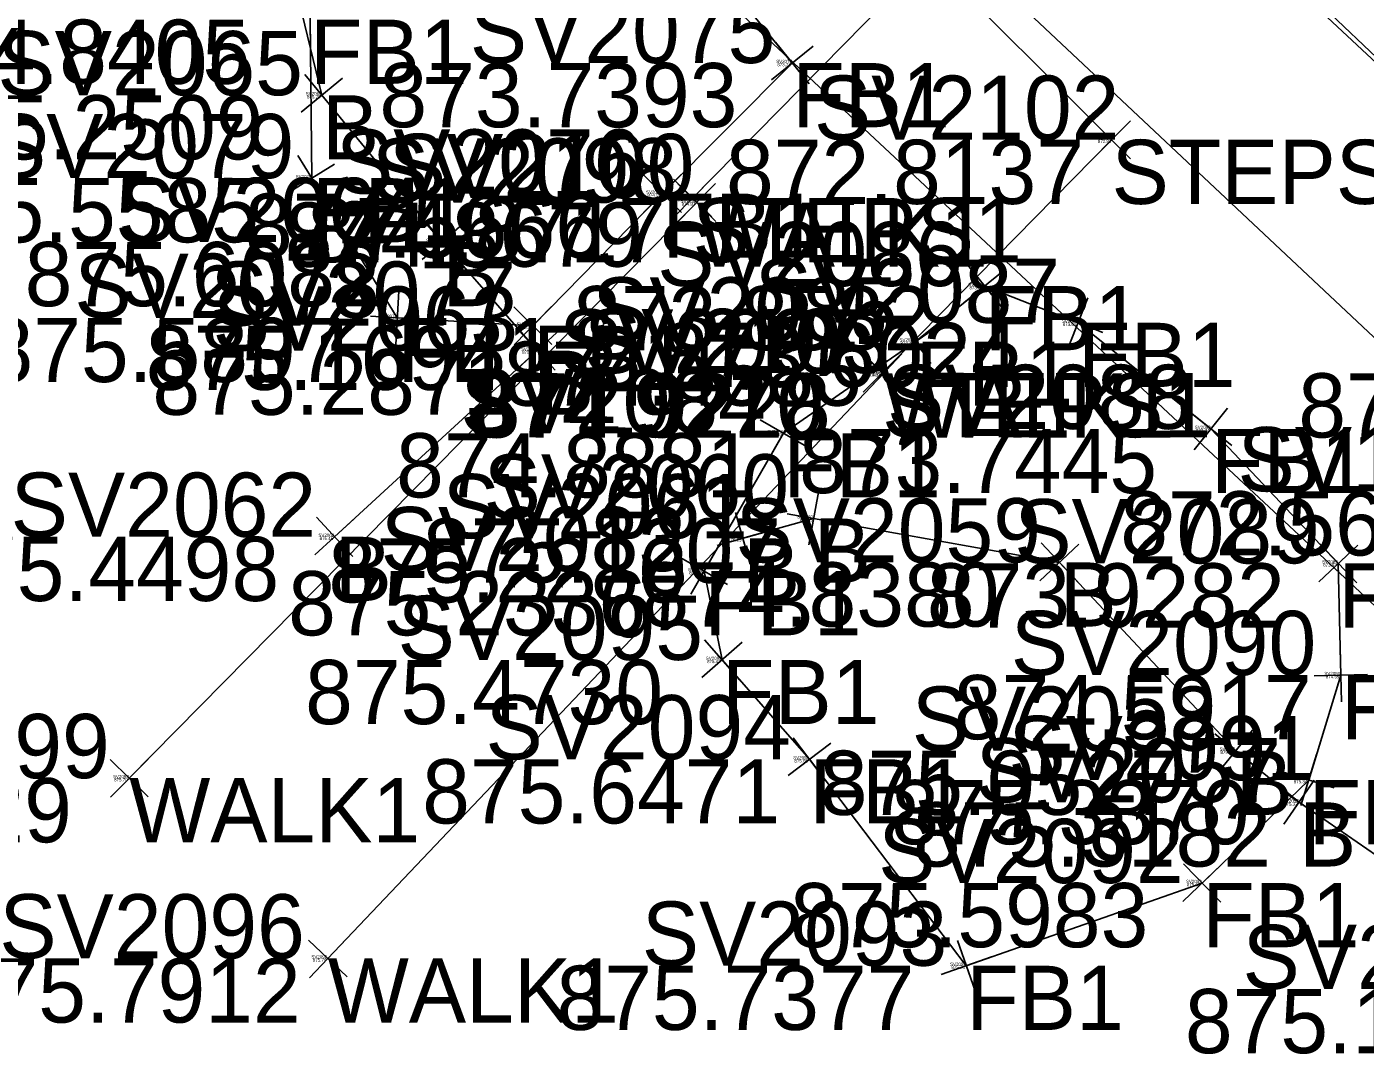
# Model space of a CAD drawing. Extents: x 1469677 to 1493262, y 375219 to 389293.
# Drawn here: x 1480055.3 to 1480080.32, y 379461.81 to 379481.19 of the extents above; entities that cross this region are included whole.
import ezdxf

# ---------------------------------------------------------------- set-up
doc = ezdxf.new("R2010")
doc.units = 0
for name, color, linetype in [('DR_X_Drive_Pipe', 7, 'Continuous'), ('DV_X_Lot_Line', 7, 'Continuous'), ('DV_X_Text', 7, 'Continuous'), ('GK_Visualization', 7, 'Continuous'), ('PNTELEV', 7, 'Continuous'), ('Property', 7, 'Continuous'), ('RW_P_Esmt_SW', 7, 'Continuous'), ('SV_X_Mon_Cells_Found', 7, 'Continuous'), ('text', 7, 'Continuous'), ('Text Property', 7, 'Continuous')]:
    doc.layers.add(name, color=color, linetype=linetype)

msp = doc.modelspace()

# ---------------------------------------------------------------- linework, layer by layer
at = {"layer": 'DR_X_Drive_Pipe'}
msp.add_lwpolyline([(1480134.739, 379430.559), (1480121.485, 379441.998), (1480113.085, 379450.369), (1480106.418, 379456.915), (1480094.539, 379467.985), (1480089.15, 379472.551), (1480086.751, 379474.713), (1480073.459, 379487.337), (1480068.123, 379493.187), (1480050.678, 379510.207), (1480044.404, 379515.873)], dxfattribs=at)
at = {"layer": 'DV_X_Lot_Line'}
for points in [[(1480132.903, 379425.968), (1480114.834, 379442.96), (1480103.251, 379453.811), (1480091.01, 379465.628), (1480083.545, 379472.507), (1480065.123, 379489.824), (1480051.079, 379503.111), (1480050.67, 379503.609), (1480040.657, 379513.03), (1480041.273, 379513.837), (1480027.417, 379527.179), (1480013.329, 379540.204)], [(1480053.564, 379505.61), (1480071.797, 379488.664), (1480089.369, 379472.273), (1480095.978, 379465.936)], [(1480067.823, 379477.906), (1480057.214, 379467.144)], [(1480060.926, 379463.774), (1480071.315, 379474.711)]]:
    msp.add_lwpolyline(points, dxfattribs=at)
at = {"layer": 'PNTELEV'}
for p, q in [((1480060.6, 379480.825), (1480060.588, 379481.825)), ((1480069.295, 379480.903), (1480069.923, 379480.125)), ((1480069.998, 379480.828), (1480069.22, 379480.2)), ((1480069.609, 379480.514), (1480069.609, 379480.514)), ((1480060.429, 379479.595), (1480061.203, 379480.229)), ((1480061.133, 379479.525), (1480060.499, 379480.299)), ((1480060.816, 379479.912), (1480060.816, 379479.912)), ((1480075.224, 379479.432), (1480075.932, 379478.725)), ((1480075.931, 379479.432), (1480075.225, 379478.725)), ((1480075.578, 379479.079), (1480075.578, 379479.079)), ((1480060.201, 379478.101), (1480061.053, 379478.623)), ((1480060.888, 379477.935), (1480060.366, 379478.788)), ((1480060.627, 379478.362), (1480060.627, 379478.362)), ((1480067.535, 379477.72), (1480066.827, 379478.426)), ((1480067.534, 379478.427), (1480066.828, 379477.719)), ((1480067.396, 379477.633), (1480068.096, 379478.347)), ((1480067.389, 379478.34), (1480068.103, 379477.64)), ((1480068.179, 379477.554), (1480067.467, 379478.257)), ((1480068.174, 379478.262), (1480067.472, 379477.549)), ((1480067.181, 379478.073), (1480067.181, 379478.073)), ((1480067.746, 379477.99), (1480067.746, 379477.99)), ((1480067.823, 379477.906), (1480067.823, 379477.906)), ((1480062.687, 379476.839), (1480063.439, 379477.497)), ((1480063.392, 379476.792), (1480062.734, 379477.544)), ((1480063.063, 379477.168), (1480063.063, 379477.168)), ((1480072.816, 379476.031), (1480073.596, 379476.658)), ((1480072.893, 379476.734), (1480073.519, 379475.955)), ((1480073.206, 379476.344), (1480073.206, 379476.344)), ((1480062.196, 379475.251), (1480062.254, 379476.249)), ((1480075.134, 379476.123), (1480074.768, 379475.192)), ((1480065.116, 379475.253), (1480064.402, 379475.953)), ((1480065.109, 379475.96), (1480064.409, 379475.246)), ((1480074.486, 379475.841), (1480075.416, 379475.475)), ((1480062.724, 379475.721), (1480061.726, 379475.779)), ((1480062.225, 379475.75), (1480062.225, 379475.75)), ((1480064.759, 379475.603), (1480064.759, 379475.603)), ((1480071.504, 379475.022), (1480072.326, 379475.591)), ((1480071.63, 379475.718), (1480072.2, 379474.896)), ((1480074.951, 379475.658), (1480074.951, 379475.658)), ((1480064.47, 379474.799), (1480065.206, 379475.476)), ((1480064.5, 379475.505), (1480065.176, 379474.769)), ((1480064.838, 379475.137), (1480064.838, 379475.137)), ((1480071.915, 379475.307), (1480071.915, 379475.307)), ((1480071.644, 379474.366), (1480070.932, 379475.067)), ((1480071.639, 379475.073), (1480070.937, 379474.36)), ((1480070.952, 379475.056), (1480071.678, 379474.367)), ((1480070.971, 379474.349), (1480071.659, 379475.074)), ((1480071.288, 379474.717), (1480071.288, 379474.717)), ((1480071.315, 379474.711), (1480071.315, 379474.711)), ((1480069.008, 379473.842), (1480069.876, 379473.344)), ((1480069.193, 379473.16), (1480069.691, 379474.027)), ((1480077.045, 379473.985), (1480077.827, 379473.361)), ((1480077.748, 379474.064), (1480077.124, 379473.283)), ((1480069.442, 379473.593), (1480069.442, 379473.593)), ((1480077.436, 379473.673), (1480077.436, 379473.673)), ((1480069.92, 379471.507), (1480070.096, 379472.491)), ((1480068.82, 379471.147), (1480068.55, 379472.11)), ((1480070.5, 379471.911), (1480069.516, 379472.087)), ((1480060.685, 379471.318), (1480061.421, 379471.994)), ((1480060.715, 379472.024), (1480061.391, 379471.288)), ((1480070.008, 379471.999), (1480070.008, 379471.999)), ((1480061.053, 379471.656), (1480061.053, 379471.656)), ((1480069.167, 379471.764), (1480068.203, 379471.494)), ((1480068.685, 379471.629), (1480068.685, 379471.629)), ((1480067.712, 379470.581), (1480068.21, 379471.448)), ((1480074.239, 379470.836), (1480074.969, 379471.519)), ((1480074.946, 379470.813), (1480074.262, 379471.543)), ((1480080.179, 379471.503), (1480079.453, 379470.816)), ((1480079.472, 379471.523), (1480080.16, 379470.797)), ((1480067.527, 379471.263), (1480068.395, 379470.765)), ((1480074.604, 379471.178), (1480074.604, 379471.178)), ((1480079.816, 379471.16), (1480079.816, 379471.16)), ((1480067.961, 379471.014), (1480067.961, 379471.014)), ((1480067.921, 379469.024), (1480068.671, 379469.685)), ((1480068.626, 379468.979), (1480067.966, 379469.73)), ((1480068.296, 379469.354), (1480068.296, 379469.354)), ((1480079.853, 379469.57), (1480079.875, 379468.571)), ((1480080.364, 379469.082), (1480079.364, 379469.059)), ((1480079.864, 379469.071), (1480079.864, 379469.071)), ((1480070.232, 379467.099), (1480069.628, 379467.895)), ((1480078.287, 379467.341), (1480077.511, 379467.973)), ((1480077.583, 379467.269), (1480078.215, 379468.044)), ((1480069.532, 379467.194), (1480070.328, 379467.799)), ((1480077.899, 379467.657), (1480077.899, 379467.657)), ((1480079.41, 379467.587), (1480079.118, 379466.63)), ((1480057.57, 379466.793), (1480056.858, 379467.495)), ((1480057.565, 379467.5), (1480056.863, 379466.788)), ((1480069.93, 379467.497), (1480069.93, 379467.497)), ((1480057.214, 379467.144), (1480057.214, 379467.144)), ((1480079.742, 379466.962), (1480078.786, 379467.255)), ((1480078.799, 379466.281), (1480079.367, 379467.104)), ((1480079.264, 379467.108), (1480079.264, 379467.108)), ((1480079.495, 379466.409), (1480078.671, 379466.976)), ((1480079.083, 379466.692), (1480079.083, 379466.692)), ((1480077.632, 379465.531), (1480076.912, 379464.836)), ((1480077.619, 379464.824), (1480076.925, 379465.543)), ((1480077.272, 379465.183), (1480077.272, 379465.183)), ((1480060.563, 379464.118), (1480061.289, 379463.429)), ((1480060.582, 379463.411), (1480061.27, 379464.136)), ((1480073.027, 379463.165), (1480072.697, 379464.109)), ((1480060.926, 379463.774), (1480060.926, 379463.774)), ((1480073.334, 379463.802), (1480072.39, 379463.471)), ((1480072.862, 379463.637), (1480072.862, 379463.637))]:
    msp.add_line(p, q, dxfattribs=at)
at = {"layer": 'Property'}
msp.add_lwpolyline([(1480067.746, 379477.99), (1480072.165, 379482.489), (1480075.578, 379479.079), (1480071.288, 379474.717)], dxfattribs=at)
at = {"layer": 'SV_X_Mon_Cells_Found'}
msp.add_lwpolyline([(1477164.629, 382297.849), (1479615.888, 379904.59), (1480413.414, 379159.216)], dxfattribs=at)
at = {"layer": 'text'}
for points in [[(1480061.053, 379471.656), (1480064.838, 379475.137), (1480063.063, 379477.168), (1480060.816, 379479.912), (1480059.959, 379483.437), (1480053.932, 379487.957), (1480050.898, 379492.776), (1480048.55, 379495.74), (1480045.746, 379494.465)], [(1480079.005, 379447.144), (1480081.842, 379450.534), (1480085.618, 379454.399), (1480087.323, 379457.733), (1480087.179, 379459.291), (1480084.148, 379463.202), (1480079.083, 379466.692), (1480077.899, 379467.657), (1480074.604, 379471.178), (1480070.008, 379471.999), (1480068.685, 379471.629)]]:
    msp.add_lwpolyline(points, dxfattribs=at)
at = {"layer": 'Text Property'}
for points in [[(1480060.934, 379485.44), (1480063.531, 379485.366), (1480068.028, 379482.471), (1480069.609, 379480.514), (1480067.181, 379478.073), (1480064.759, 379475.603), (1480062.225, 379475.75), (1480060.627, 379478.362), (1480060.594, 379481.325), (1480060.963, 379484.307), (1480062.027, 379485.899)], [(1480067.961, 379471.014), (1480069.442, 379473.593), (1480071.915, 379475.307), (1480073.206, 379476.344), (1480074.951, 379475.658), (1480077.436, 379473.673), (1480079.816, 379471.16), (1480079.864, 379469.071), (1480079.264, 379467.108), (1480077.272, 379465.183), (1480072.862, 379463.637), (1480069.93, 379467.497), (1480068.296, 379469.354)]]:
    msp.add_lwpolyline(points, close=True, dxfattribs=at)

# ---------------------------------------------------------------- texts
at = {"layer": 'DV_X_Text'}
for s, height, p in [('874.8405', 1.2, (1480052.781, 379480.125)), ('873.7393', 1.2, (1480061.89, 379479.314)), ('873.74', 0.06, (1480069.329, 379480.454)), ('875.2509', 1.2, (1480053.031, 379478.712)), ('875.25', 0.06, (1480060.537, 379479.852)), ('872.8137', 1.2, (1480068.37, 379477.879)), ('872.81', 0.06, (1480075.321, 379479.019)), ('875.5585', 1.2, (1480052.946, 379477.162)), ('875.56', 0.06, (1480060.343, 379478.302)), ('874.5666', 1.2, (1480059.377, 379476.873)), ('874.8679', 1.2, (1480060.123, 379476.706)), ('874.8717', 1.2, (1480060.547, 379476.79)), ('874.57', 0.06, (1480066.9, 379478.013)), ('874.87', 0.06, (1480067.465, 379477.93)), ('874.87', 0.06, (1480067.542, 379477.846)), ('875.6082', 1.2, (1480055.259, 379475.968)), ('875.61', 0.06, (1480062.804, 379477.108)), ('873.8582', 1.2, (1480065.515, 379475.144)), ('873.86', 0.06, (1480072.921, 379476.284)), ('875.5897', 1.2, (1480054.525, 379474.55)), ('875.1694', 1.2, (1480057.522, 379474.403)), ('875.59', 0.06, (1480061.944, 379475.69)), ('875.17', 0.06, (1480064.503, 379475.543)), ('873.6024', 1.2, (1480067.147, 379474.458)), ('873.60', 0.06, (1480074.664, 379475.598)), ('875.2871', 1.2, (1480057.646, 379473.937)), ('874.4585', 1.2, (1480064.215, 379474.107)), ('875.29', 0.06, (1480064.558, 379475.077)), ('874.46', 0.06, (1480071.63, 379475.247)), ('874.9270', 1.2, (1480063.512, 379473.517)), ('874.9228', 1.2, (1480063.634, 379473.511)), ('874.93', 0.06, (1480071.006, 379474.657)), ('874.92', 0.06, (1480071.034, 379474.651)), ('872.5987', 1.2, (1480079.069, 379473.513)), ('874.8881', 1.2, (1480062.202, 379472.393)), ('874.89', 0.06, (1480069.161, 379473.533)), ('873.7445', 1.2, (1480069.736, 379472.473)), ('873.74', 0.06, (1480077.156, 379473.613)), ('872.5608', 1.2, (1480075.741, 379471.307)), ('875.1207', 1.2, (1480062.705, 379470.799)), ('875.12', 0.06, (1480069.752, 379471.939)), ('875.4498', 1.2, (1480053.324, 379470.456)), ('875.45', 0.06, (1480060.772, 379471.596)), ('875.2280', 1.2, (1480060.937, 379470.429)), ('875.23', 0.06, (1480068.406, 379471.569)), ('874.8380', 1.2, (1480066.79, 379469.978)), ('873.9282', 1.2, (1480072.125, 379469.96)), ('874.84', 0.06, (1480074.324, 379471.118)), ('873.93', 0.06, (1480079.534, 379471.1)), ('875.2336', 1.2, (1480060.185, 379469.814)), ('875.23', 0.06, (1480067.682, 379470.954)), ('875.4730', 1.2, (1480060.501, 379468.154)), ('875.47', 0.06, (1480068.015, 379469.294)), ('874.5917', 1.2, (1480072.627, 379467.871)), ('874.59', 0.06, (1480079.583, 379469.011)), ('875.0527', 1.2, (1480070.123, 379466.457)), ('875.05', 0.06, (1480077.613, 379467.597)), ('875.6471', 1.2, (1480062.69, 379466.297)), ('875.65', 0.06, (1480069.649, 379467.437)), ('875.7029', 1.2, (1480049.448, 379465.944)), ('875.70', 0.06, (1480056.93, 379467.084)), ('875.3370', 1.2, (1480071.46, 379465.908)), ('875.34', 0.06, (1480078.983, 379467.048)), ('875.3182', 1.2, (1480071.865, 379465.492)), ('875.32', 0.06, (1480078.802, 379466.632)), ('875.5983', 1.2, (1480069.572, 379463.983)), ('875.60', 0.06, (1480076.986, 379465.123)), ('875.7912', 1.2, (1480053.727, 379462.574)), ('875.79', 0.06, (1480060.646, 379463.714)), ('875.7377', 1.2, (1480065.2, 379462.437)), ('875.74', 0.06, (1480072.583, 379463.577)), ('875.1232', 1.2, (1480076.949, 379462.002))]:
    msp.add_text(s, height=height, dxfattribs=at).set_placement(p)
at = {"layer": 'GK_Visualization'}
for s, p in [('FB1', (1480060.594, 379480.125)), ('FB1', (1480069.609, 379479.314)), ('B', (1480060.816, 379478.712)), ('STEPS1', (1480075.578, 379477.879)), ('FB1', (1480060.627, 379477.162)), ('FB1', (1480067.181, 379476.873)), ('STEPS1', (1480067.746, 379476.79)), ('WALK1', (1480067.823, 379476.706)), ('B', (1480063.063, 379475.968)), ('FB1', (1480073.206, 379475.144)), ('FB1', (1480062.225, 379474.55)), ('FB1', (1480064.759, 379474.403)), ('FB1', (1480074.951, 379474.458)), ('B', (1480064.838, 379473.937)), ('FB1', (1480071.915, 379474.107)), ('WALK1', (1480071.315, 379473.511)), ('STEPS1', (1480071.288, 379473.517)), ('FB1', (1480069.442, 379472.393)), ('FB1', (1480077.436, 379472.473)), ('B', (1480070.008, 379470.799)), ('B', (1480061.053, 379470.456)), ('B', (1480068.685, 379470.429)), ('B', (1480074.604, 379469.978)), ('FB1', (1480079.816, 379469.96)), ('FB1', (1480067.961, 379469.814)), ('FB1', (1480068.296, 379468.154)), ('FB1', (1480079.864, 379467.871)), ('B', (1480077.899, 379466.457)), ('FB1', (1480069.93, 379466.297)), ('WALK1', (1480057.214, 379465.944)), ('FB1', (1480079.264, 379465.908)), ('B', (1480079.083, 379465.492)), ('FB1', (1480077.272, 379463.983)), ('WALK1', (1480060.926, 379462.574)), ('FB1', (1480072.862, 379462.437))]:
    msp.add_text(s, height=1.2, dxfattribs=at).set_placement(p)
at = {"layer": 'RW_P_Esmt_SW'}
for s, height, p in [('SV2075', 1.2, (1480063.581, 379480.514)), ('SV2065', 1.2, (1480054.75, 379479.912)), ('SV2075', 0.06, (1480069.308, 379480.514)), ('SV2102', 1.2, (1480070.014, 379479.079)), ('SV2065', 0.06, (1480060.513, 379479.912)), ('SV2079', 1.2, (1480054.59, 379478.362)), ('SV2076', 1.2, (1480061.078, 379478.073)), ('SV2098', 1.2, (1480061.748, 379477.906)), ('SV2100', 1.2, (1480062.068, 379477.99)), ('SV2102', 0.06, (1480075.3, 379479.079)), ('SV2064', 1.2, (1480057.007, 379477.168)), ('SV2079', 0.06, (1480060.325, 379478.362)), ('SV2076', 0.06, (1480066.876, 379478.073)), ('SV2100', 0.06, (1480067.462, 379477.99)), ('SV2098', 0.06, (1480067.519, 379477.906)), ('SV2086', 1.2, (1480067.084, 379476.344)), ('SV2064', 0.06, (1480062.76, 379477.168)), ('SV2078', 1.2, (1480056.188, 379475.75)), ('SV2087', 1.2, (1480068.904, 379475.658)), ('SV2077', 1.2, (1480058.731, 379475.603)), ('SV2063', 1.2, (1480058.772, 379475.137)), ('SV2085', 1.2, (1480065.868, 379475.307)), ('SV2086', 0.06, (1480072.9, 379476.344)), ('SV2097', 1.2, (1480065.249, 379474.711)), ('SV2103', 1.2, (1480065.714, 379474.717)), ('SV2078', 0.06, (1480061.923, 379475.75)), ('SV2077', 0.06, (1480064.458, 379475.603)), ('SV2087', 0.06, (1480074.649, 379475.658)), ('SV2085', 0.06, (1480071.613, 379475.307)), ('SV2063', 0.06, (1480064.535, 379475.137)), ('SV2088', 1.2, (1480071.38, 379473.673)), ('SV2084', 1.2, (1480063.405, 379473.593)), ('SV2103', 0.06, (1480071.009, 379474.717)), ('SV2097', 0.06, (1480071.012, 379474.711)), ('SV2084', 0.06, (1480069.14, 379473.593)), ('SV2088', 0.06, (1480077.133, 379473.673)), ('SV1940', 1.2, (1480077.933, 379472.507)), ('SV2060', 1.2, (1480063.838, 379471.999)), ('SV2062', 1.2, (1480054.997, 379471.656)), ('SV2061', 1.2, (1480063.071, 379471.629)), ('SV2059', 1.2, (1480068.548, 379471.178)), ('SV2089', 1.2, (1480073.76, 379471.16)), ('SV2083', 1.2, (1480061.914, 379471.014)), ('SV2060', 0.06, (1480069.7, 379471.999)), ('SV2062', 0.06, (1480060.75, 379471.656)), ('SV2061', 0.06, (1480068.404, 379471.629)), ('SV2059', 0.06, (1480074.301, 379471.178)), ('SV2089', 0.06, (1480079.513, 379471.16)), ('SV2083', 0.06, (1480067.659, 379471.014)), ('SV2095', 1.2, (1480062.23, 379469.354)), ('SV2090', 1.2, (1480073.694, 379469.071)), ('SV2095', 0.06, (1480067.993, 379469.354)), ('SV2090', 0.06, (1480079.556, 379469.071)), ('SV2058', 1.2, (1480071.843, 379467.657)), ('SV2094', 1.2, (1480063.874, 379467.497)), ('SV2099', 1.2, (1480051.139, 379467.144)), ('SV2091', 1.2, (1480073.65, 379467.108)), ('SV2057', 1.2, (1480073.036, 379466.692)), ('SV2058', 0.06, (1480077.596, 379467.657)), ('SV2094', 0.06, (1480069.627, 379467.497)), ('SV2099', 0.06, (1480056.91, 379467.144)), ('SV2091', 0.06, (1480078.983, 379467.108)), ('SV2057', 0.06, (1480078.781, 379466.692)), ('SV2092', 1.2, (1480071.216, 379465.183)), ('SV2092', 0.06, (1480076.969, 379465.183)), ('SV2096', 1.2, (1480054.785, 379463.774)), ('SV2093', 1.2, (1480066.796, 379463.637)), ('SV2056', 1.2, (1480078.026, 379463.202)), ('SV2096', 0.06, (1480060.619, 379463.774)), ('SV2093', 0.06, (1480072.559, 379463.637))]:
    msp.add_text(s, height=height, dxfattribs=at).set_placement(p)

doc.saveas('drawing.dxf')
